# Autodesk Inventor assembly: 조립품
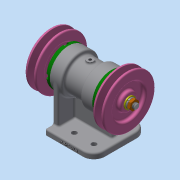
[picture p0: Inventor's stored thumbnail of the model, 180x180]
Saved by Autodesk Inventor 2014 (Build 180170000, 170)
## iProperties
Created: 2020-06
Part Number: 조립품
Document SubType Name: Assembly
Designer: kh
Author: kh
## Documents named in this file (12)
- C:\Users\kh\Desktop\700606V1030\조립품.iam
- C:\Users\kh\Desktop\700606V1030\본체.ipt
- C:\Users\kh\Desktop\700606V1030\베어링 6204.ipt
- C:\Users\kh\Desktop\700606V1030\축.ipt
- C:\Users\kh\Desktop\700606V1030\커버.ipt
- C:\Users\kh\Desktop\700606V1030\오일 실 20 32 5.ipt
- C:\Users\kh\Desktop\700606V1030\V-벨트풀리.ipt
- C:\Users\kh\Desktop\700606V1030\키 5x5x12.ipt
- C:\Users\kh\Desktop\700606V1030\스프링 와셔 10.ipt
- C:\Users\kh\Desktop\700606V1030\평면 와셔 10x21.ipt
- C:\Users\kh\Desktop\700606V1030\너트 M10.ipt
- C:\Users\kh\Desktop\700606V1030\볼트 M4.ipt
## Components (2 placed, 1 different names)
1. V-벨트풀리:1 — Mate:19, Angle:2, Mate:26, Mate:31
2. V-벨트풀리:2 — Mate:18, Angle:1, Mate:27, Mate:35
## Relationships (8: Mate 6, Angle 2)
- Mate:18: V-벨트풀리:2
- Mate:19: V-벨트풀리:1
- Angle:1: V-벨트풀리:2
- Angle:2: V-벨트풀리:1
- Mate:26: V-벨트풀리:1
- Mate:27: V-벨트풀리:2
- Mate:31: V-벨트풀리:1
- Mate:35: V-벨트풀리:2
